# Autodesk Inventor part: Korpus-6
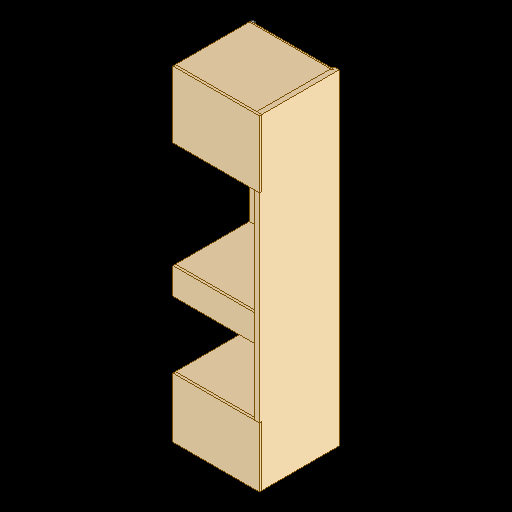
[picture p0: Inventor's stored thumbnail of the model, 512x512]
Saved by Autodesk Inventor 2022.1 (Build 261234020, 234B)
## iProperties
Created: 2021-09
Part Number: Korpus-6
Material: Generisch
Document SubType Name: Modeling
Designer: J. Ruhl
Density: 1 g/cm^3
Appearance: Vorgabe
Author: J. Ruhl
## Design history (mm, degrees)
sketch "Skizze11"
  geometry: L1 (0, 0)-(19, 0); L2 (19, 0)-(19, 600); L3 (19, 600)-(0, 600); L4 (0, 600)-(0, 0); L5 (631, 0)-(669, 0); L6 (669, 0)-(669, 600); L7 (669, 600)-(631, 600); L8 (631, 600)-(631, 0); L9 (19, 0)-(631, 0); L10 (631, 0)-(631, 19); L11 (631, 19)-(19, 19); L12 (19, 19)-(19, 0); L13 (19, 585)-(641, 585); L14 (641, 585)-(641, 575); L15 (641, 575)-(19, 575); L16 (19, 575)-(19, 585); L17 (19, 585)-(19, 575); L18 (640, 585)-(640, 575); L19 (631, 0)-(631, 0); 7 further points
  constraints: 38 end point, 8 parallel, 5 horizontal, 4 perpendicular, 4 point on line, 3 collinear, 2 vertical
  dimensions: "d132" = 19 distance of L3.end L2.end; "d133" = 600 distance of L2.end L1.end; "d134" = 38 distance of L7.end L6.end; "d137" = 19 distance of L10.end L9.end; "d138" = 10 distance of L13.end L14.end; "d139" = 15 distance between parallel lines of L13 L7; "d140" = 10 distance between parallel lines of L8 L14; "d141" = 0 distance between parallel lines of L2 L16; "d142" = 0 distance between parallel lines of L16 L17; "d143" = 1 distance between parallel lines of L14 L18; "d198" = 650 distance between parallel lines of L6 L2
extrude "Extrusion18" new body sketch "Skizze11" distance "d144" = 2450; taper "d145" = 0 deg
extrude "Extrusion19" new body sketch "Skizze11" stored distance "d146" = 1950; taper "d147" = 0 deg
extrude "Extrusion20" new body sketch "Skizze11" distance "d148" = 19; taper "d149" = 0 deg
extrude "Extrusion21" new body sketch "Skizze11" stored distance "d150" = 1950; taper "d151" = 0 deg
extrude "Extrusion22" new body sketch "Skizze11" distance "d152" = 450; taper "d153" = 0 deg
pattern_linear "Rechteckige Anordnung3" dims "d156" = 431
pattern_linear "Rechteckige Anordnung4" dims "d159" = 519
pattern_linear "Rechteckige Anordnung5" dims "d162" = 181
extrude "Extrusion23" new body sketch "Skizze11" stored distance "d163" = 400; taper "d164" = 0 deg
sketch "Skizze12"
  geometry: L1 (-19, 19)-(-631, 19) reference; L2 (-19, 575)-(-19, 19) reference; C1 r 5 at (-47, 47); C2 r 5 at (-47, 111); C3 r 5 at (-111, 47); C4 r 5 at (-111, 111); 2 further points
  constraints: 4 centre point, 2 horizontal alignment, 2 vertical alignment
  dimensions: "d165" = 10 diameter of C1; "d166" = 10 diameter of C2; "d167" = 10 diameter of C3; "d168" = 10 diameter of C4; "d169" = 28 distance from line of L1 C3.centre; "d170" = 28 distance from line of L2 C2.centre; "d173" = 64 distance of C4.centre C3.centre; "d174" = 64 distance of C4.centre C2.centre
extrude "Extrusion24" cut sketch "Skizze12" distance "d171" = 11; taper "d172" = 0 deg
pattern_linear "Rechteckige Anordnung6" dims "d177" = 511, "d180" = 440
sketch "Skizze15"
  geometry: L1 (0, 10)-(20, 10); L2 (20, 10)-(20, 25); L3 (20, 25)-(0, 25); L4 (0, 25)-(0, 10); 1 further point
  constraints: 8 end point, 2 parallel, 1 horizontal, 1 perpendicular
  dimensions: "d205" = 20 distance of L3.end L2.end; "d206" = 15 distance of L2.end L1.end
extrude "Extrusion32" new body sketch "Skizze15" stored distance "d207" = 10; taper "d208" = 0 deg
sketch "Skizze16"
  geometry: L1 (431, 556)-(431, 0) reference; L2 (431, 0)-(450, 0) reference; L3 (450, 556)-(450, 0) reference; L4 (431, 556)-(450, 556) reference; L5 (950, 556)-(950, 0) reference; L6 (950, 0)-(969, 0) reference; L7 (969, 556)-(969, 0) reference; L8 (950, 556)-(969, 556) reference; L9 (1131, 556)-(1131, 0) reference; L10 (1131, 0)-(1150, 0) reference; L11 (1150, 556)-(1150, 0) reference; L12 (1131, 556)-(1150, 556) reference; L13 (19, 556)-(431, 556); L14 (431, 556)-(431, 0); L15 (431, 0)-(19, 0); L16 (19, 0)-(19, 556); L17 (969, 556)-(1131, 556); L18 (1131, 556)-(1131, 0); L19 (1131, 0)-(969, 0); L20 (969, 0)-(969, 556); 1 further point
  constraints: 16 end point, 4 parallel, 2 horizontal, 2 perpendicular
  node "Projizierte Kontur12"
  node "Projizierte Kontur13"
  node "Projizierte Kontur14"
extrude "Extrusion33" new body sketch "Skizze16" distance "d209" = 19; taper "d210" = 0 deg
extrude "Extrusion34" new body sketch "Skizze16" distance "d211" = 19; taper "d212" = 0 deg
sketch "Skizze17"
  geometry: L1 (612, 0)-(0, 0) reference; L2 (612, 556)-(612, 0) reference; L3 (0, 0)-(0, 556) reference; L4 (612, 28)-(0, 28); L5 (0, 28)-(0, 45); L6 (0, 45)-(612, 45); L7 (612, 45)-(612, 28); 1 further point
  constraints: 8 end point, 2 collinear, 2 parallel, 1 horizontal, 1 perpendicular
  dimensions: "d213" = 17 distance of L4.end L5.end; "d214" = 28 distance between parallel lines of L1 L4
extrude "Extrusion35" cut sketch "Skizze17" distance "d215" = 9; taper "d216" = 0 deg
pattern_linear "Rechteckige Anordnung9"
feature "Körper verschieben2"
node "Direktbearbeitung5"
sketch "Skizze19"
  geometry: L1 (-2450, 0)-(-1950, 0); L2 (-1950, 0)-(-1950, 19); L3 (-1950, 19)-(-2450, 19); L4 (-2450, 19)-(-2450, 0); L5 (-1950, 19)-(-1950, 0) reference; L6 (0, 0)-(-450, 0); L7 (-450, 0)-(-450, 19); L8 (-450, 19)-(0, 19); L9 (0, 19)-(0, 0); L10 (-450, 0)-(-450, 19) reference
  constraints: 16 end point, 4 parallel, 2 collinear, 2 horizontal, 2 perpendicular
  dimensions: "d239" = 19 distance of L1.end L2.end; "d245" = 19 distance of L6.end L7.end
extrude "Extrusion37" cut sketch "Skizze19" stored distance "d240" = 9; taper "d241" = 0 deg
node "Direktbearbeitung6"
node "Volumenkörper13"
node "Volumenkörper14"
node "Volumenkörper15"
node "Volumenkörper16"
node "Volumenkörper17"
feature "Anordnung von Volumenkörper15:1"
node "Volumenkörper18"
feature "Anordnung von Volumenkörper18:2"
node "Volumenkörper19"
feature "Anordnung von Volumenkörper19:3"
node "Volumenkörper20"
node "Volumenkörper21"
node "Volumenkörper31"
node "Volumenkörper32"
node "Volumenkörper33"
feature "Anordnung von Volumenkörper20:6"
node "Volumenkörper35"
feature "Anordnung von Volumenkörper33:7"
node "Volumenkörper37"
feature "Anordnung von Volumenkörper19:8"
node "Volumenkörper34"
feature "Anordnung von Volumenkörper21:9"
node "Volumenkörper36"
feature "Verschieben9" dims "d231" = 300
feature "Verschieben10" dims "d234" = 300
feature "Verschieben11" dims "d244" = 38
feature "Verschieben12" dims "d248" = 38
other parameters: "d226" = 0, "d227" = 0, "d229" = 0, "d230" = 0, "d232" = 0, "d233" = 0, "d242" = 0, "d243" = 0, "d246" = 0, "d247" = 0
